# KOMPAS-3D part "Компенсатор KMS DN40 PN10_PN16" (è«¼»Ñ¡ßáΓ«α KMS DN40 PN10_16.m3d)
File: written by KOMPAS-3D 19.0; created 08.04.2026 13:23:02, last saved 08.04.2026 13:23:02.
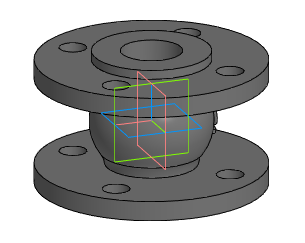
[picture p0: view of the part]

Document properties: Автор: Энергия; Полное имя файла: Z:\3.Личные\kachalov\3d для проектировщиков\7.1 Компенсатор\stp_Компенсатор KSM\Компенсатор KMS DN40 PN10_16.m3d

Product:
- Part/product: Компенсатор KMS DN40 PN10_PN16

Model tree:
1. Операция без истории:1  (labels: Компенсатор KMS DN40 PN10_PN16)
